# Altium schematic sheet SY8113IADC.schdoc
size 127 x 101 mm
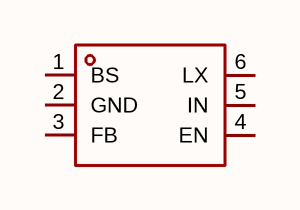
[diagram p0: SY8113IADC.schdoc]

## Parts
U?  sy8113iadc  [TSOT-23-6_L2.9-W1.6-P0.95-LS2.8-BL]  (value not drawn)

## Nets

Not connected (* = marked no-connect by the designer): U? 1(BS) 2(GND) 3(FB) 4(EN) 5(IN) 6(LX)

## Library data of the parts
U? = sy8113iadc: 功能类型:降压型;工作电压:4.2V~18V;输出电压:-;输出电流:3A;输出类型:可调;; Manufacturer: Silergy(矽力杰); AddInBom: yes; ModelId: 2c4039b5b88644c1bda4b4ba9e971667; ModelName: TSOT-23-6_L2.9-W1.6-H1.1-LS2.8-P0.95; ModelTransform: 110.236,114.173,0,90,0,0,0,0,0; Function: 降压型; Output Current: 3A; Frequency - Switching: 500kHz; Synchronous Rectifier: 是; Number of Outputs: 1; Topology: 降压式; Quiescent Current: 200uA; Switch tube (built-in/external): 内置; Output Type: 可调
